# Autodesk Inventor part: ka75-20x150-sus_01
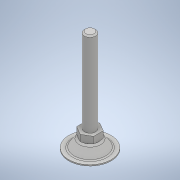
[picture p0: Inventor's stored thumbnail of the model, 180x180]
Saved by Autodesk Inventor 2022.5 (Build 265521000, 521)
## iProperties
Part Number: ka75-20x150-sus_01
Material: 一般
Document SubType Name: Modeling
Designer: ImaoCorp
Density: 1 g/cm^3
Appearance: 既定
Author: ImaoCorp
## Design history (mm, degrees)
feature "ka75-20x150-sus_01"
node "ソリッド1"
